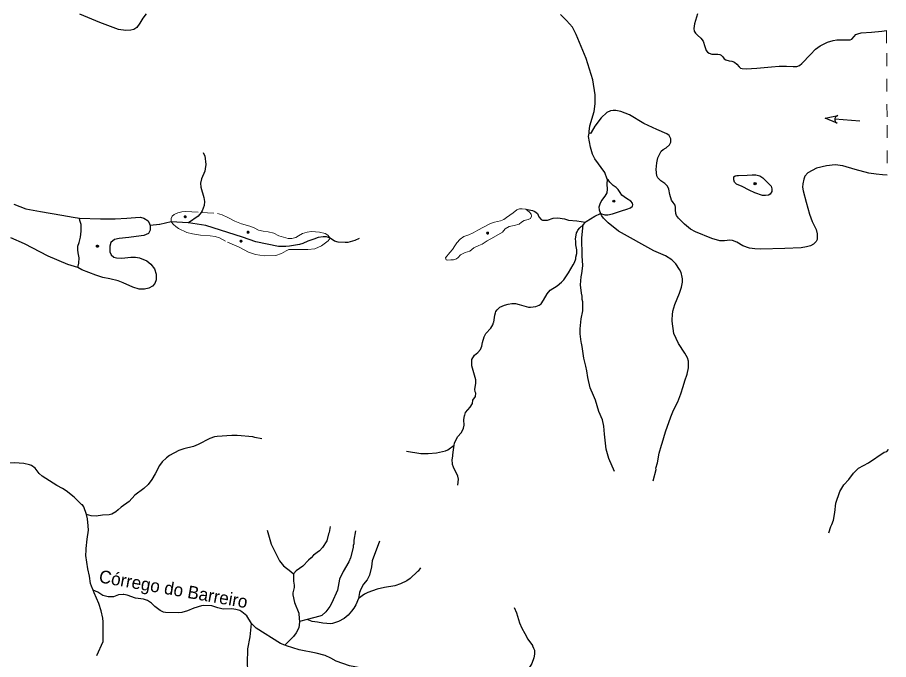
# Model space of a CAD drawing. Extents: x 396 to 422.2, y 7649.8 to 7677.6.
# Drawn here: x 415.26 to 422.11, y 7663.27 to 7668.32 of the extents above; entities that cross this region are included whole.
import ezdxf
from ezdxf.enums import TextEntityAlignment as Align

# ---------------------------------------------------------------- set-up
doc = ezdxf.new("R2010")
doc.units = 0
doc.header["$LTSCALE"] = 0.032
doc.header["$PDMODE"] = 32
doc.header["$PDSIZE"] = 0.016
doc.linetypes.add('LONG_DASHED', pattern=[7.5, 6, -1.5])
doc.linetypes.add('SHORT_DASHED', pattern=[2.7, 1.5, -1.2])
for name, color, linetype, lineweight in [('10', 7, 'Continuous', 25), ('2', 7, 'Continuous', 25), ('21', 7, 'SHORT_DASHED', 13), ('3', 7, 'LONG_DASHED', 25), ('62', 7, 'SHORT_DASHED', 13), ('7', 7, 'Continuous', 25)]:
    doc.layers.add(name, color=color, linetype=linetype, lineweight=lineweight)
doc.layers.add('54', color=7, linetype='Continuous')
doc.layers.add('61', color=7, linetype='Continuous')

msp = doc.modelspace()

# ---------------------------------------------------------------- linework, layer by layer
at = {"layer": '10'}
msp.add_line((421.8826, 7667.5052), (421.6851, 7667.5229), dxfattribs=at)
msp.add_lwpolyline([(421.7096, 7667.5499), (421.7016, 7667.5469), (421.6965, 7667.5439), (421.6901, 7667.5369), (421.6855, 7667.5264), (421.6851, 7667.5229), (421.6856, 7667.5145), (421.688, 7667.5073), (421.6915, 7667.5008), (421.697, 7667.4958), (421.7045, 7667.4914), (421.6106, 7667.5295)], close=True, dxfattribs=at)
at = {"layer": '2'}
for points in [[(416.2745, 7668.3507), (416.247, 7668.3163), (416.2234, 7668.276), (416.1998, 7668.2426), (416.1781, 7668.2268), (416.1545, 7668.2209), (416.1132, 7668.218), (416.0562, 7668.2268), (415.9087, 7668.2819), (415.7524, 7668.3478)], [(420.6069, 7668.3498), (420.5833, 7668.2711), (420.5784, 7668.2347), (420.5813, 7668.2141), (420.5902, 7668.1983), (420.6059, 7668.1836), (420.6325, 7668.159), (420.6502, 7668.1364), (420.6649, 7668.0931), (420.6747, 7668.0616), (420.6856, 7668.0489), (420.6974, 7668.04), (420.718, 7668.0322), (420.7416, 7668.0322), (420.7662, 7668.0322), (420.7809, 7668.0312), (420.7927, 7668.0253), (420.8045, 7668.0125), (420.8163, 7667.9977), (420.8301, 7667.9879), (420.8557, 7667.982), (420.8763, 7667.9771), (420.897, 7667.9692), (420.9166, 7667.9545), (420.9343, 7667.9338), (420.9451, 7667.924), (420.9589, 7667.9201), (420.9904, 7667.9171), (421.073, 7667.922), (421.187, 7667.9338), (421.249, 7667.9378), (421.307, 7667.9378), (421.3591, 7667.9358), (421.3876, 7667.9358), (421.4083, 7667.9437), (421.4279, 7667.9594), (421.4958, 7668.0312), (421.5332, 7668.0725), (421.5705, 7668.098), (421.6285, 7668.1275), (421.6728, 7668.1413), (421.7023, 7668.1462), (421.7161, 7668.1472), (421.7377, 7668.1472), (421.7652, 7668.1462), (421.7859, 7668.1462), (421.8075, 7668.1462), (421.8193, 7668.1521), (421.837, 7668.1728), (421.8517, 7668.1875), (421.8655, 7668.1934), (421.893, 7668.2003), (421.9747, 7668.2072), (422.0553, 7668.215), (422.0927, 7668.219)], [(419.7564, 7667.4117), (419.7544, 7667.4264), (419.7613, 7667.4707), (419.7937, 7667.5818), (419.8026, 7667.6418), (419.8035, 7667.7136), (419.7839, 7667.8306), (419.7308, 7667.9987), (419.6541, 7668.1875), (419.6246, 7668.2455), (419.5764, 7668.2986), (419.5292, 7668.3439)], [(422.0981, 7667.0813), (422.0612, 7667.0833), (422.0101, 7667.0892), (421.953, 7667.097), (421.8449, 7667.1265), (421.7485, 7667.155), (421.6875, 7667.1629), (421.6207, 7667.1541), (421.543, 7667.1364), (421.4732, 7667.101), (421.4506, 7667.0754), (421.4417, 7667.0518), (421.4338, 7667.0144), (421.4319, 7666.9869), (421.4358, 7666.9594), (421.4614, 7666.8709), (421.4869, 7666.7755), (421.5076, 7666.7165), (421.54, 7666.6536), (421.5479, 7666.6201), (421.5479, 7666.5759), (421.5381, 7666.5602), (421.5184, 7666.5385), (421.4948, 7666.5257), (421.4624, 7666.5179), (421.4201, 7666.51), (421.2942, 7666.5061), (421.1005, 7666.5012), (421.0572, 7666.5031), (421.0159, 7666.508), (420.9619, 7666.5277), (420.9157, 7666.5562), (420.8822, 7666.568), (420.8616, 7666.571), (420.8183, 7666.567), (420.7819, 7666.567), (420.719, 7666.5847), (420.5902, 7666.6359), (420.5508, 7666.6575), (420.5046, 7666.6968), (420.4565, 7666.744), (420.4407, 7666.7657), (420.4358, 7666.7814), (420.4338, 7666.8089), (420.4329, 7666.8286), (420.4319, 7666.8453), (420.4161, 7666.866), (420.4024, 7666.8856), (420.3896, 7666.9289), (420.3807, 7666.9712), (420.3699, 7666.9948), (420.3493, 7667.0154), (420.3178, 7667.0371), (420.2962, 7667.0616), (420.2883, 7667.0764), (420.2814, 7667.1265), (420.2863, 7667.1786), (420.2952, 7667.218), (420.307, 7667.2455), (420.3208, 7667.2701), (420.3375, 7667.2829), (420.3601, 7667.2966), (420.3866, 7667.3202), (420.3975, 7667.3419), (420.3975, 7667.3665), (420.3837, 7667.393), (420.366, 7667.4078), (420.2883, 7667.4412), (420.1841, 7667.4874), (420.071, 7667.5562), (420.0032, 7667.5828), (419.9648, 7667.5916), (419.9451, 7667.5916), (419.9235, 7667.5867), (419.894, 7667.5739), (419.8488, 7667.5317), (419.8006, 7667.4677), (419.7711, 7667.4176), (419.7652, 7667.4097), (419.7564, 7667.4117)], [(419.8956, 7667.0494), (419.8943, 7667.0119), (419.8969, 7666.9718), (419.893, 7666.9433), (419.8775, 7666.9174), (419.8529, 7666.8825), (419.8387, 7666.8553), (419.8322, 7666.8294), (419.8348, 7666.8087), (419.8454, 7666.78)], [(419.8454, 7666.78), (419.8788, 7666.7699), (419.9008, 7666.7699), (419.9383, 7666.7777), (420.0094, 7666.8023), (420.0521, 7666.8139), (420.0806, 7666.8243), (420.0948, 7666.8372), (420.0974, 7666.8476), (420.0961, 7666.8618), (420.0819, 7666.8786), (420.0483, 7666.8993), (420.012, 7666.9252), (419.9978, 7666.9459), (419.9836, 7666.9692), (419.9668, 7666.9847), (419.9448, 7667.0015), (419.9189, 7667.0274), (419.9046, 7667.0442), (419.8956, 7667.0494)], [(421.1168, 7666.923), (421.0565, 7666.9428), (421.0126, 7666.9652), (420.9584, 7666.9927), (420.9128, 7667.0125), (420.8965, 7667.0263), (420.8922, 7667.0461), (420.8922, 7667.0676), (420.9016, 7667.0771), (420.9145, 7667.0805), (420.9283, 7667.0797)], [(420.9283, 7667.0797), (420.9963, 7667.0831), (421.0359, 7667.084), (421.0651, 7667.0848), (421.0961, 7667.0771), (421.1194, 7667.0616), (421.1426, 7667.0375), (421.1641, 7667.0177), (421.1865, 7666.9962), (421.1916, 7666.9738), (421.1899, 7666.9523), (421.1779, 7666.9316), (421.165, 7666.9256), (421.1417, 7666.923), (421.1168, 7666.923)], [(415.2342, 7666.8532), (415.3286, 7666.8178), (415.4436, 7666.7952), (415.6108, 7666.7676), (415.7012, 7666.7529), (415.7504, 7666.745)], [(415.7366, 7666.3556), (415.6589, 7666.3792), (415.5036, 7666.4451), (415.3168, 7666.5415), (415.2096, 7666.5906)]]:
    msp.add_lwpolyline(points, dxfattribs=at)
msp.add_point((419.9494, 7666.8777), dxfattribs=at)
at = {"layer": '21'}
for points in [[(416.4712, 7666.7154), (416.4702, 7666.7407), (416.4783, 7666.7596), (416.4944, 7666.773), (416.5227, 7666.7865), (416.555, 7666.7932), (416.5833, 7666.7973), (416.7049, 7666.7898)], [(416.7049, 7666.7898), (416.8349, 7666.7811), (416.8712, 7666.7703), (416.9156, 7666.7488), (416.9708, 7666.7192), (417.0219, 7666.699), (417.0879, 7666.6815), (417.1215, 7666.6681), (417.1578, 7666.6492), (417.1942, 7666.6412), (417.2319, 7666.6358), (417.2776, 7666.6264), (417.3153, 7666.6062), (417.353, 7666.5941), (417.3906, 7666.5833), (417.4176, 7666.5833), (417.4498, 7666.5927), (417.47, 7666.6048), (417.5023, 7666.6237), (417.54, 7666.6344), (417.5736, 7666.6385), (417.6355, 7666.6331), (417.68, 7666.6223), (417.7028, 7666.6102), (417.721, 7666.5869)], [(418.6272, 7666.4313), (418.66, 7666.4736), (418.6823, 7666.4969), (418.6992, 7666.5276), (418.7151, 7666.5498), (418.7426, 7666.5795), (418.7712, 7666.6006), (418.8093, 7666.6123), (418.8442, 7666.6281), (418.8802, 7666.6504), (418.9236, 7666.6737), (418.9807, 7666.7022), (419.0114, 7666.7118), (419.059, 7666.7223), (419.0834, 7666.7329), (419.1067, 7666.7499), (419.131, 7666.7668), (419.1575, 7666.7869), (419.186, 7666.8091), (419.2083, 7666.8176), (419.2284, 7666.8176), (419.2566, 7666.8134)], [(419.2566, 7666.8134), (419.2855, 7666.7922), (419.2993, 7666.7742), (419.3025, 7666.7594), (419.2951, 7666.7425), (419.2771, 7666.734), (419.2443, 7666.7255), (419.2231, 7666.7128), (419.2061, 7666.698), (419.1649, 7666.6864)], [(417.721, 7666.5869), (417.7042, 7666.5645), (417.653, 7666.5268), (417.6006, 7666.5026), (417.5454, 7666.4985), (417.4768, 7666.4972), (417.4243, 7666.4972), (417.396, 7666.4985), (417.3745, 7666.4864), (417.3368, 7666.4649), (417.2924, 7666.4501), (417.2022, 7666.4474), (417.1323, 7666.4582), (417.0785, 7666.4757), (417.0044, 7666.516), (416.8968, 7666.5631), (416.851, 7666.59), (416.816, 7666.6008), (416.7757, 7666.6062), (416.7017, 7666.6102), (416.6384, 7666.6196), (416.5927, 7666.6304), (416.5281, 7666.664), (416.5066, 7666.6788), (416.4891, 7666.6936), (416.4712, 7666.7154)], [(419.1649, 7666.6864), (419.1257, 7666.6779), (419.095, 7666.6599), (419.0739, 7666.6345), (419.0051, 7666.5953), (418.9543, 7666.5657), (418.9151, 7666.5392), (418.8886, 7666.5297), (418.8484, 7666.5096), (418.8167, 7666.4842), (418.7817, 7666.4736), (418.7447, 7666.4556), (418.7267, 7666.4355), (418.7119, 7666.4249), (418.6897, 7666.4175), (418.6685, 7666.4165), (418.6431, 7666.4133), (418.6325, 7666.4165), (418.6293, 7666.4249), (418.6272, 7666.4313)]]:
    msp.add_lwpolyline(points, dxfattribs=at)
for p in [(416.5806, 7666.7555), (417.0744, 7666.6331), (417.0192, 7666.5631), (418.9574, 7666.6271)]:
    msp.add_point(p, dxfattribs=at)
at = {"layer": '3'}
for points in [[(415.7366, 7666.3556), (415.7447, 7666.3897), (415.7461, 7666.4311), (415.7392, 7666.4711), (415.7364, 7666.4946), (415.7364, 7666.5249), (415.7475, 7666.5539), (415.7585, 7666.5939), (415.764, 7666.6409), (415.7626, 7666.6947), (415.753, 7666.725), (415.7504, 7666.745)], [(415.7504, 7666.745), (415.9145, 7666.7375), (416.029, 7666.7375), (416.1229, 7666.743), (416.1905, 7666.7499), (416.2305, 7666.7513), (416.2553, 7666.7444), (416.2885, 7666.7237), (416.3009, 7666.7002), (416.3064, 7666.6863)], [(416.3064, 7666.6863), (416.305, 7666.6491), (416.2912, 7666.6243), (416.2553, 7666.6077), (416.1946, 7666.5995), (416.138, 7666.5912), (416.0607, 7666.5843), (416.0249, 7666.5774), (415.9959, 7666.5525), (415.9876, 7666.5249), (415.989, 7666.4794), (416, 7666.4559), (416.0193, 7666.4366), (416.04, 7666.4311), (416.0828, 7666.4297), (416.1532, 7666.4366), (416.1891, 7666.4366), (416.2222, 7666.4311), (416.2788, 7666.409), (416.3092, 7666.3814), (416.3381, 7666.3455), (416.3533, 7666.3027), (416.3533, 7666.2586), (416.3409, 7666.231), (416.3243, 7666.2103), (416.2954, 7666.1937), (416.2595, 7666.1854), (416.2195, 7666.1854), (416.1684, 7666.2006), (416.0939, 7666.2351), (416.0538, 7666.2503), (415.989, 7666.2669), (415.9338, 7666.2779), (415.8786, 7666.2958), (415.822, 7666.3179), (415.7695, 7666.3372), (415.7366, 7666.3556)]]:
    msp.add_lwpolyline(points, dxfattribs=at)
msp.add_point((415.8906, 7666.5236), dxfattribs=at)
at = {"layer": '54'}
msp.add_point((421.0587, 7667.0151), dxfattribs=at)
at = {"layer": '62'}
msp.add_lwpolyline([(422.0927, 7668.219), (422.0936, 7668.0399), (422.0963, 7667.4752), (422.0981, 7667.0813)], dxfattribs=at)
at = {"layer": '7'}
for p, q in [((419.7079, 7666.6916), (419.7262, 7666.7117)), ((417.5382, 7663.5885), (417.4794, 7663.5733))]:
    msp.add_line(p, q, dxfattribs=at)
for points in [[(419.8956, 7667.0494), (419.8781, 7667.1023), (419.7994, 7667.2109), (419.7809, 7667.246), (419.7647, 7667.3018), (419.7491, 7667.3849), (419.7564, 7667.4117)], [(416.7222, 7667.261), (416.7324, 7667.2363), (416.7361, 7667.2346), (416.7417, 7667.1649), (416.7386, 7667.1317), (416.7339, 7667.1132), (416.7083, 7667.0519), (416.7011, 7667.02), (416.7029, 7666.9865), (416.7258, 7666.9077), (416.7313, 7666.8761), (416.729, 7666.8446), (416.7138, 7666.8016), (416.7049, 7666.7898)], [(416.7049, 7666.7898), (416.682, 7666.7597), (416.606, 7666.7069)], [(419.2566, 7666.8134), (419.3102, 7666.8055), (419.3292, 7666.7966), (419.3486, 7666.7811), (419.3589, 7666.7557), (419.3782, 7666.7327), (419.3878, 7666.7278), (419.4281, 7666.7278), (419.4732, 7666.7437), (419.5086, 7666.7453), (419.5605, 7666.7382), (419.594, 7666.7295), (419.6589, 7666.7237), (419.7262, 7666.7117)], [(419.7262, 7666.7117), (419.732, 7666.7181), (419.8007, 7666.7592), (419.8454, 7666.78)], [(420.2582, 7664.6792), (420.2807, 7664.7682), (420.2802, 7664.7784), (420.2912, 7664.8195), (420.3058, 7664.8971), (420.3229, 7664.9593), (420.3298, 7664.974), (420.3554, 7665.0633), (420.3972, 7665.1831), (420.4186, 7665.2343), (420.4515, 7665.3), (420.4767, 7665.3629), (420.4934, 7665.4204), (420.5063, 7665.465), (420.526, 7665.5179), (420.5262, 7665.5188), (420.5352, 7665.5675), (420.5353, 7665.6193), (420.529, 7665.6448), (420.5078, 7665.683), (420.4568, 7665.7589), (420.4207, 7665.8374), (420.4079, 7665.9341), (420.4093, 7665.9959), (420.4125, 7666.0024), (420.4127, 7666.0126), (420.4287, 7666.0662), (420.4663, 7666.1543), (420.4818, 7666.2011), (420.4891, 7666.2397), (420.489, 7666.2659), (420.486, 7666.2797), (420.478, 7666.316), (420.4656, 7666.3404), (420.4354, 7666.3852), (420.4041, 7666.4166), (420.3548, 7666.4481), (420.2631, 7666.4883), (419.9858, 7666.6405), (419.9036, 7666.7063), (419.8678, 7666.7436), (419.8543, 7666.7615), (419.8454, 7666.78)], [(416.4712, 7666.7154), (416.3823, 7666.6948), (416.3779, 7666.6938), (416.3064, 7666.6863)], [(416.606, 7666.7069), (416.6049, 7666.7061), (416.4712, 7666.7154)], [(417.721, 7666.5869), (417.6906, 7666.5961), (417.6641, 7666.597), (417.6265, 7666.5907), (417.591, 7666.5781), (417.5447, 7666.5619), (417.5038, 7666.5444), (417.4789, 7666.5364), (417.4, 7666.5243), (417.3718, 7666.52), (417.3126, 7666.5216), (417.1345, 7666.5582), (417.0318, 7666.5954), (416.7419, 7666.6859), (416.606, 7666.7069)], [(418.6939, 7664.9585), (418.6963, 7664.9738), (418.7204, 7665.0242), (418.7527, 7665.0599), (418.7667, 7665.092), (418.7729, 7665.1169), (418.7714, 7665.1591), (418.7745, 7665.1931), (418.7778, 7665.1956), (418.7845, 7665.2164), (418.8188, 7665.2579), (418.8382, 7665.2882), (418.8407, 7665.3143), (418.862, 7665.3431), (418.8654, 7665.3669), (418.8591, 7665.3788), (418.8567, 7665.4005), (418.8638, 7665.4431), (418.8638, 7665.4725), (418.8336, 7665.5823), (418.8336, 7665.6325), (418.8532, 7665.6667), (418.8803, 7665.6883), (418.9018, 7665.7114), (418.9124, 7665.7373), (418.9166, 7665.7668), (418.9302, 7665.8111), (418.9445, 7665.8381), (418.9812, 7665.8788), (418.9978, 7665.9052), (419.0027, 7665.9237), (419.0058, 7665.9263), (419.0137, 7665.9813), (419.0197, 7666.0009), (419.0224, 7666.0098), (419.0316, 7666.0239), (419.0523, 7666.0445), (419.0896, 7666.0601), (419.1194, 7666.0684), (419.1485, 7666.0723), (419.1768, 7666.0722), (419.2064, 7666.0664), (419.2773, 7666.0451), (419.2934, 7666.0436), (419.3351, 7666.0494), (419.3619, 7666.0602), (419.3772, 7666.0706), (419.3975, 7666.0981), (419.4248, 7666.1482), (419.4478, 7666.1769), (419.5032, 7666.2123), (419.5367, 7666.2395), (419.555, 7666.2587), (419.5935, 7666.3134), (419.6299, 7666.3782), (419.6392, 7666.3947), (419.6517, 7666.4251), (419.6518, 7666.4379), (419.6581, 7666.4663), (419.6581, 7666.4956), (419.6518, 7666.5345), (419.6517, 7666.5635), (419.6486, 7666.5786), (419.655, 7666.6286), (419.661, 7666.6357), (419.6662, 7666.6496), (419.6823, 7666.6691), (419.7079, 7666.6916)], [(419.9531, 7664.7516), (419.9107, 7664.8544), (419.8889, 7664.929), (419.875, 7665.0455), (419.871, 7665.1093), (419.8592, 7665.1596), (419.8309, 7665.2244), (419.8048, 7665.313), (419.7897, 7665.3496), (419.7644, 7665.411), (419.7443, 7665.4914), (419.7377, 7665.5434), (419.7288, 7665.5815), (419.714, 7665.6445), (419.7011, 7665.7348), (419.6944, 7665.7616), (419.6916, 7665.7728), (419.6853, 7665.8355), (419.6853, 7665.8752), (419.6926, 7665.9522), (419.7043, 7666.0148), (419.7044, 7666.0872), (419.7013, 7666.1039), (419.7012, 7666.1297), (419.6949, 7666.1549), (419.6884, 7666.219), (419.6932, 7666.2825), (419.6988, 7666.308), (419.7055, 7666.3681), (419.7059, 7666.3718), (419.6997, 7666.4484), (419.6965, 7666.5894), (419.7079, 7666.6916)], [(417.9474, 7666.5846), (417.913, 7666.5682), (417.8582, 7666.5536), (417.8374, 7666.5524), (417.7828, 7666.5563), (417.7546, 7666.5644), (417.721, 7666.5869)], [(415.8045, 7664.4143), (415.784, 7664.4737), (415.7728, 7664.4897), (415.7691, 7664.4906), (415.7091, 7664.5512), (415.6462, 7664.6007), (415.6169, 7664.6193), (415.5709, 7664.6431), (415.456, 7664.7169), (415.4333, 7664.7378), (415.4011, 7664.7779), (415.372, 7664.7987), (415.3567, 7664.8057), (415.312, 7664.8156), (415.2398, 7664.821), (415.142, 7664.8154), (415.0037, 7664.7972), (414.9708, 7664.7986), (414.9436, 7664.8081), (414.896, 7664.8516), (414.8267, 7664.9505), (414.7979, 7664.987), (414.7816, 7665.0153)], [(417.183, 7665.0101), (417.1284, 7665.0187), (417.1112, 7665.0239), (416.9877, 7665.0363), (416.9479, 7665.0363), (416.8331, 7665.0275), (416.8117, 7665.0237), (416.7741, 7665.0115), (416.6828, 7664.9642), (416.6467, 7664.9489), (416.569, 7664.9307), (416.5316, 7664.9174), (416.4572, 7664.8786), (416.4341, 7664.8609), (416.3987, 7664.8273), (416.3774, 7664.7989), (416.3435, 7664.7352), (416.3194, 7664.6901), (416.2892, 7664.6493), (416.2542, 7664.6182), (416.1856, 7664.5664), (416.1393, 7664.5169), (416.0764, 7664.471), (416.0546, 7664.4516), (416.0354, 7664.4346), (416.005, 7664.4172), (415.982, 7664.4111), (415.9306, 7664.4095), (415.8815, 7664.4001), (415.841, 7664.4032), (415.8045, 7664.4143)], [(418.3204, 7664.912), (418.4329, 7664.8928), (418.4913, 7664.8929), (418.5557, 7664.8983), (418.6274, 7664.9157), (418.6436, 7664.9235), (418.6939, 7664.9585)], [(418.7232, 7664.6454), (418.729, 7664.6923), (418.7233, 7664.7152), (418.6881, 7664.7858), (418.6821, 7664.8071), (418.6789, 7664.8501), (418.682, 7664.8549), (418.6854, 7664.9044), (418.6939, 7664.9585)], [(421.6394, 7664.2692), (421.6537, 7664.319), (421.6628, 7664.3364), (421.6744, 7664.3696), (421.6868, 7664.4303), (421.6933, 7664.5041), (421.7264, 7664.5951), (421.7569, 7664.6476), (421.7959, 7664.6892), (421.8319, 7664.7402), (421.8727, 7664.7791), (421.9508, 7664.82), (422.073, 7664.9031), (422.095, 7664.9102), (422.1081, 7664.9263), (422.1083, 7664.9265)], [(415.8008, 7664.0921), (415.8014, 7664.1327), (415.8027, 7664.1468), (415.8094, 7664.2205), (415.8197, 7664.2903), (415.819, 7664.3254), (415.8126, 7664.38), (415.8045, 7664.4143)], [(417.7192, 7664.3191), (417.7114, 7664.2719), (417.7057, 7664.2629), (417.6947, 7664.2081), (417.6607, 7664.1545), (417.6359, 7664.129), (417.59, 7664.0949), (417.5717, 7664.0727), (417.5493, 7664.0544), (417.506, 7664.0094), (417.4517, 7663.971), (417.4304, 7663.9482)], [(417.2243, 7664.2913), (417.2563, 7664.1799), (417.3226, 7664.0508), (417.3537, 7664.0114), (417.4111, 7663.9666), (417.4304, 7663.9482)], [(417.9178, 7664.2865), (417.9069, 7664.2129), (417.9067, 7664.1833), (417.9016, 7664.1712), (417.9003, 7664.1544), (417.8787, 7664.0746), (417.8669, 7664.0435), (417.8225, 7663.9671), (417.7938, 7663.9069), (417.7775, 7663.8198), (417.732, 7663.7193), (417.717, 7663.6921), (417.6867, 7663.6495), (417.6537, 7663.6214), (417.6391, 7663.6148), (417.5382, 7663.5885)], [(418.1071, 7664.2047), (418.0504, 7664.0503), (418.044, 7664.0016), (418.0296, 7663.9381), (418.0095, 7663.902), (417.9828, 7663.8659), (417.9604, 7663.8269), (417.9516, 7663.8), (417.9423, 7663.7544)], [(415.857, 7663.8203), (415.8429, 7663.851), (415.8373, 7663.8729), (415.8293, 7663.9302), (415.8143, 7663.9873), (415.8008, 7664.0921)], [(418.4285, 7663.9943), (418.4104, 7663.9678), (418.406, 7663.9667), (418.3483, 7663.9116), (418.3218, 7663.8929), (418.2737, 7663.8688), (418.2272, 7663.8547), (418.1458, 7663.8416), (418.0886, 7663.8281), (418.0166, 7663.8017), (417.9884, 7663.7876), (417.9423, 7663.7544)], [(417.4304, 7663.9482), (417.4316, 7663.89), (417.4379, 7663.8581), (417.4359, 7663.8404), (417.4252, 7663.7998), (417.4261, 7663.7836), (417.4387, 7663.7228), (417.4734, 7663.638), (417.4762, 7663.5936), (417.4794, 7663.5733)], [(417.1023, 7663.5567), (417.0641, 7663.6172), (417.0253, 7663.6504), (417.0091, 7663.6589), (416.9798, 7663.6687), (416.9482, 7663.6735), (416.8793, 7663.6703), (416.8379, 7663.6794), (416.791, 7663.6956), (416.7265, 7663.6989), (416.7084, 7663.6959), (416.649, 7663.6773), (416.5976, 7663.6569), (416.5546, 7663.644), (416.5263, 7663.64), (416.4255, 7663.6439), (416.4094, 7663.6475), (416.3835, 7663.6587), (416.3411, 7663.692), (416.3161, 7663.7178), (416.2847, 7663.7372), (416.252, 7663.7481), (416.1888, 7663.756), (416.124, 7663.7801), (416.0977, 7663.7842), (416.0925, 7663.785), (416.0569, 7663.7826), (416.0183, 7663.7668), (415.9753, 7663.7683), (415.9326, 7663.7785), (415.8928, 7663.8028), (415.857, 7663.8203)], [(415.885, 7663.3056), (415.935, 7663.4154), (415.9371, 7663.4839), (415.9354, 7663.5705), (415.9321, 7663.5992), (415.9192, 7663.6566), (415.901, 7663.7136), (415.8639, 7663.7987), (415.857, 7663.8203)], [(417.9423, 7663.7544), (417.9209, 7663.7035), (417.9047, 7663.6791), (417.8876, 7663.6534), (417.8624, 7663.6242), (417.8289, 7663.5977), (417.7851, 7663.5727), (417.7393, 7663.5577), (417.7238, 7663.5554), (417.6625, 7663.5594), (417.6205, 7663.5688), (417.5779, 7663.5719), (417.5382, 7663.5885)], [(419.1658, 7663.6844), (419.1843, 7663.6415), (419.207, 7663.5626), (419.2258, 7663.5203), (419.2495, 7663.4776), (419.2741, 7663.4332), (419.309, 7663.3852), (419.3109, 7663.3808), (419.3181, 7663.3633), (419.3247, 7663.3476), (419.3247, 7663.3169), (419.3209, 7663.2878), (419.3047, 7663.244), (419.2429, 7663.1414)], [(417.0742, 7663.1392), (417.0725, 7663.1946), (417.071, 7663.2419), (417.0726, 7663.3573), (417.0916, 7663.4526), (417.1023, 7663.5567)], [(417.3642, 7663.387), (417.3287, 7663.4014), (417.1375, 7663.5216), (417.1023, 7663.5567)], [(417.4794, 7663.5733), (417.4793, 7663.5731), (417.4791, 7663.5714), (417.473, 7663.5223), (417.4514, 7663.4848), (417.4307, 7663.4557), (417.3642, 7663.387)], [(418.3705, 7663.1225), (418.3423, 7663.1336), (418.3314, 7663.1444), (418.3052, 7663.1608), (418.2654, 7663.1766), (418.2286, 7663.1821), (418.1374, 7663.1838), (418.0236, 7663.1957), (417.8713, 7663.2249), (417.8197, 7663.2426), (417.7677, 7663.2605), (417.7263, 7663.2836), (417.6795, 7663.3051), (417.6089, 7663.3233), (417.4768, 7663.3498), (417.3759, 7663.3823), (417.3642, 7663.387)]]:
    msp.add_lwpolyline(points, dxfattribs=at)

# ---------------------------------------------------------------- texts
at = {"layer": '61'}
msp.add_text('Córrego do Barreiro', height=0.1, rotation=350.047, dxfattribs=at).set_placement((416.4793, 7663.7793), align=Align.CENTER)

doc.saveas('drawing.dxf')
